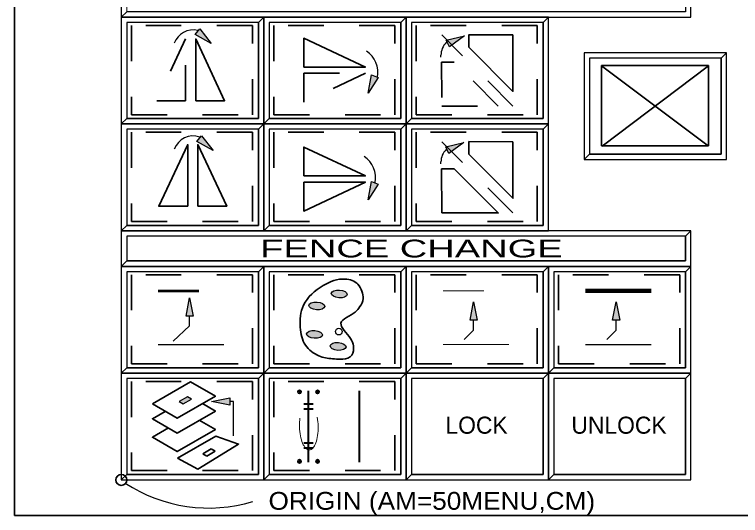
# Model space of a CAD drawing. Extents: x 95906.8 to 95923.6, y 90964.8 to 90972.8.
# Drawn here: x 95906.832 to 95908.871, y 90964.762 to 90966.169 of the extents above; entities that cross this region are included whole.
import ezdxf
from ezdxf.enums import TextEntityAlignment as Align

# ---------------------------------------------------------------- set-up
doc = ezdxf.new("R2010")
doc.units = 0
doc.header["$LTSCALE"] = 0.019
doc.header["$PDMODE"] = 32
doc.header["$PDSIZE"] = 0.0095
for name, pattern in [('DOTTED', [1.5, 0.3, -1.2]), ('LONG_DASHED', [7.5, 6, -1.5]), ('MEDIUM_DASHED', [4.5, 3, -1.5])]:
    doc.linetypes.add(name, pattern=pattern)
for name, color, linetype, lineweight in [('1', 7, 'Continuous', 25), ('11', 7, 'Continuous', 25), ('12', 7, 'Continuous', 25), ('16', 7, 'Continuous', 25), ('18', 7, 'Continuous', 25), ('2', 7, 'Continuous', 13), ('3', 7, 'Continuous', 25), ('6', 7, 'Continuous', 35), ('7', 7, 'Continuous', 35)]:
    doc.layers.add(name, color=color, linetype=linetype, lineweight=lineweight)

msp = doc.modelspace()

# ---------------------------------------------------------------- hatches: boundary and pattern name
at = {"layer": '6'}
for points in [[(95907.3851, 90966.0877), (95907.3396, 90966.1133), (95907.3529, 90966.1287)], [(95908.0958, 90966.1092), (95908.0537, 90966.0783), (95908.0451, 90966.0968)], [(95907.8257, 90965.9486), (95907.8349, 90966), (95907.8539, 90965.9925)], [(95907.3901, 90965.7871), (95907.3445, 90965.8126), (95907.3579, 90965.8282)], [(95908.0947, 90965.8094), (95908.0526, 90965.7785), (95908.044, 90965.797)], [(95907.8257, 90965.6486), (95907.8349, 90965.7), (95907.8539, 90965.6925)], [(95907.314, 90965.3216), (95907.3242, 90965.3728), (95907.3344, 90965.3216)], [(95908.1219, 90965.3617), (95908.1321, 90965.3105), (95908.1117, 90965.3105)], [(95908.5219, 90965.3617), (95908.5321, 90965.3105), (95908.5117, 90965.3105)], [(95907.3058, 90965.0753), (95907.3293, 90965.0889), (95907.3181, 90965.0953), (95907.2946, 90965.0817)], [(95907.3857, 90965.0817), (95907.4369, 90965.0919), (95907.4369, 90965.0715)]]:
    msp.add_hatch(color=256, dxfattribs=at).paths.add_polyline_path(points)
h = msp.add_hatch(color=256, dxfattribs=at)
edge = h.paths.add_edge_path()
edge.add_ellipse((95907.7443, 90965.3842), major_axis=(-0.0223, 0.0015), ratio=0.490241, start_angle=0, end_angle=360)
h = msp.add_hatch(color=256, dxfattribs=at)
edge = h.paths.add_edge_path()
edge.add_ellipse((95907.6812, 90965.3504), major_axis=(-0.0223, 0.0015), ratio=0.490241, start_angle=0, end_angle=360)
h = msp.add_hatch(color=256, dxfattribs=at)
edge = h.paths.add_edge_path()
edge.add_ellipse((95907.6751, 90965.2705), major_axis=(-0.0223, 0.0015), ratio=0.490241, start_angle=0, end_angle=360)
h = msp.add_hatch(color=256, dxfattribs=at)
edge = h.paths.add_edge_path()
edge.add_ellipse((95907.7412, 90965.2366), major_axis=(-0.0223, 0.0015), ratio=0.490241, start_angle=0, end_angle=360)

# ---------------------------------------------------------------- linework, layer by layer
at = {"layer": '1'}
for points in [[(95907.1323, 90966.1617), (95908.7323, 90966.1617), (95908.7323, 90966.2617), (95907.1323, 90966.2617)], [(95907.1323, 90965.8617), (95907.5323, 90965.8617), (95907.5323, 90966.1617), (95907.1323, 90966.1617)], [(95907.5323, 90965.8617), (95907.9323, 90965.8617), (95907.9323, 90966.1617), (95907.5323, 90966.1617)], [(95907.9323, 90965.8617), (95908.3323, 90965.8617), (95908.3323, 90966.1617), (95907.9323, 90966.1617)], [(95908.4323, 90965.7617), (95908.8323, 90965.7617), (95908.8323, 90966.0617), (95908.4323, 90966.0617)], [(95907.1323, 90965.5617), (95907.5323, 90965.5617), (95907.5323, 90965.8617), (95907.1323, 90965.8617)], [(95907.5323, 90965.5617), (95907.9323, 90965.5617), (95907.9323, 90965.8617), (95907.5323, 90965.8617)], [(95907.9323, 90965.5617), (95908.3323, 90965.5617), (95908.3323, 90965.8617), (95907.9323, 90965.8617)], [(95907.1323, 90965.4617), (95908.7323, 90965.4617), (95908.7323, 90965.5617), (95907.1323, 90965.5617)], [(95907.1323, 90965.1617), (95907.5323, 90965.1617), (95907.5323, 90965.4617), (95907.1323, 90965.4617)], [(95907.5323, 90965.1617), (95907.9323, 90965.1617), (95907.9323, 90965.4617), (95907.5323, 90965.4617)], [(95907.9323, 90965.1617), (95908.3323, 90965.1617), (95908.3323, 90965.4617), (95907.9323, 90965.4617)], [(95908.3323, 90965.1617), (95908.7323, 90965.1617), (95908.7323, 90965.4617), (95908.3323, 90965.4617)], [(95907.1323, 90964.8617), (95907.5323, 90964.8617), (95907.5323, 90965.1617), (95907.1323, 90965.1617)], [(95907.5323, 90964.8617), (95907.9323, 90964.8617), (95907.9323, 90965.1617), (95907.5323, 90965.1617)], [(95907.9323, 90964.8617), (95908.3323, 90964.8617), (95908.3323, 90965.1617), (95907.9323, 90965.1617)], [(95908.3323, 90964.8617), (95908.7323, 90964.8617), (95908.7323, 90965.1617), (95908.3323, 90965.1617)]]:
    msp.add_lwpolyline(points, close=True, dxfattribs=at)
at = {"layer": '11'}
for points in [[(95907.5473, 90965.8767), (95907.9173, 90965.8767), (95907.9173, 90966.1467), (95907.5473, 90966.1467)], [(95907.9473, 90965.8767), (95908.3173, 90965.8767), (95908.3173, 90966.1467), (95907.9473, 90966.1467)], [(95907.1473, 90965.5767), (95907.5173, 90965.5767), (95907.5173, 90965.8467), (95907.1473, 90965.8467)], [(95907.5473, 90965.5767), (95907.9173, 90965.5767), (95907.9173, 90965.8467), (95907.5473, 90965.8467)], [(95907.9473, 90965.5767), (95908.3173, 90965.5767), (95908.3173, 90965.8467), (95907.9473, 90965.8467)], [(95907.1473, 90965.1767), (95907.5173, 90965.1767), (95907.5173, 90965.4467), (95907.1473, 90965.4467)], [(95907.5473, 90965.1767), (95907.9173, 90965.1767), (95907.9173, 90965.4467), (95907.5473, 90965.4467)], [(95907.9473, 90965.1767), (95908.3173, 90965.1767), (95908.3173, 90965.4467), (95907.9473, 90965.4467)], [(95907.1473, 90964.8767), (95907.5173, 90964.8767), (95907.5173, 90965.1467), (95907.1473, 90965.1467)], [(95907.5473, 90964.8767), (95907.9173, 90964.8767), (95907.9173, 90965.1467), (95907.5473, 90965.1467)], [(95907.9473, 90964.8767), (95908.3173, 90964.8767), (95908.3173, 90965.1467), (95907.9473, 90965.1467)], [(95908.3473, 90964.8767), (95908.7173, 90964.8767), (95908.7173, 90965.1467), (95908.3473, 90965.1467)]]:
    msp.add_lwpolyline(points, close=True, dxfattribs=at)
at = {"layer": '12'}
for points in [[(95907.1473, 90965.8767), (95907.5173, 90965.8767), (95907.5173, 90966.1467), (95907.1473, 90966.1467)], [(95908.3473, 90965.1767), (95908.7173, 90965.1767), (95908.7173, 90965.4467), (95908.3473, 90965.4467)]]:
    msp.add_lwpolyline(points, close=True, dxfattribs=at)
at = {"layer": '16'}
msp.add_lwpolyline([(95908.4473, 90965.7767), (95908.8173, 90965.7767), (95908.8173, 90966.0467), (95908.4473, 90966.0467)], close=True, dxfattribs=at)
msp.add_lwpolyline([(95908.4473, 90965.7767), (95908.8173, 90965.7767), (95908.8173, 90966.0467), (95908.4473, 90966.0467)], close=True, dxfattribs=at)
at = {"layer": '18'}
msp.add_lwpolyline([(95907.1473, 90965.4767), (95908.7173, 90965.4767), (95908.7173, 90965.5467), (95907.1473, 90965.5467)], close=True, dxfattribs=at)
at = {"layer": '2'}
for points in [[(95907.1323, 90966.2617), (95907.1323, 90966.1617), (95907.1473, 90966.1767), (95907.1473, 90966.2467), (95908.7173, 90966.2467), (95908.7323, 90966.2617)], [(95907.1323, 90966.1617), (95907.1323, 90965.8617), (95907.1473, 90965.8767), (95907.1473, 90966.1467), (95907.5173, 90966.1467), (95907.5323, 90966.1617)], [(95907.5323, 90966.1617), (95907.5323, 90965.8617), (95907.5473, 90965.8767), (95907.5473, 90966.1467), (95907.9173, 90966.1467), (95907.9323, 90966.1617)], [(95907.9323, 90966.1617), (95907.9323, 90965.8617), (95907.9473, 90965.8767), (95907.9473, 90966.1467), (95908.3173, 90966.1467), (95908.3323, 90966.1617)], [(95908.4323, 90966.0617), (95908.4323, 90965.7617), (95908.4473, 90965.7767), (95908.4473, 90966.0467), (95908.8173, 90966.0467), (95908.8323, 90966.0617)], [(95907.1323, 90965.8617), (95907.1323, 90965.5617), (95907.1473, 90965.5767), (95907.1473, 90965.8467), (95907.5173, 90965.8467), (95907.5323, 90965.8617)], [(95907.5323, 90965.8617), (95907.5323, 90965.5617), (95907.5473, 90965.5767), (95907.5473, 90965.8467), (95907.9173, 90965.8467), (95907.9323, 90965.8617)], [(95907.9323, 90965.8617), (95907.9323, 90965.5617), (95907.9473, 90965.5767), (95907.9473, 90965.8467), (95908.3173, 90965.8467), (95908.3323, 90965.8617)], [(95907.1323, 90965.5617), (95907.1323, 90965.4617), (95907.1473, 90965.4767), (95907.1473, 90965.5467), (95908.7173, 90965.5467), (95908.7323, 90965.5617)], [(95907.1323, 90965.4617), (95907.1323, 90965.1617), (95907.1473, 90965.1767), (95907.1473, 90965.4467), (95907.5173, 90965.4467), (95907.5323, 90965.4617)], [(95907.5323, 90965.4617), (95907.5323, 90965.1617), (95907.5473, 90965.1767), (95907.5473, 90965.4467), (95907.9173, 90965.4467), (95907.9323, 90965.4617)], [(95907.9323, 90965.4617), (95907.9323, 90965.1617), (95907.9473, 90965.1767), (95907.9473, 90965.4467), (95908.3173, 90965.4467), (95908.3323, 90965.4617)], [(95908.3323, 90965.4617), (95908.3323, 90965.1617), (95908.3473, 90965.1767), (95908.3473, 90965.4467), (95908.7173, 90965.4467), (95908.7323, 90965.4617)], [(95907.1323, 90965.1617), (95907.1323, 90964.8617), (95907.1473, 90964.8767), (95907.1473, 90965.1467), (95907.5173, 90965.1467), (95907.5323, 90965.1617)], [(95907.5323, 90965.1617), (95907.5323, 90964.8617), (95907.5473, 90964.8767), (95907.5473, 90965.1467), (95907.9173, 90965.1467), (95907.9323, 90965.1617)], [(95907.9323, 90965.1617), (95907.9323, 90964.8617), (95907.9473, 90964.8767), (95907.9473, 90965.1467), (95908.3173, 90965.1467), (95908.3323, 90965.1617)], [(95908.3323, 90965.1617), (95908.3323, 90964.8617), (95908.3473, 90964.8767), (95908.3473, 90965.1467), (95908.7173, 90965.1467), (95908.7323, 90965.1617)]]:
    msp.add_lwpolyline(points, close=True, dxfattribs=at)
at = {"layer": '3'}
for points in [[(95907.1323, 90966.1617), (95908.7323, 90966.1617), (95908.7323, 90966.2617), (95908.7173, 90966.2467), (95908.7173, 90966.1767), (95907.1473, 90966.1767)], [(95907.1323, 90965.8617), (95907.5323, 90965.8617), (95907.5323, 90966.1617), (95907.5173, 90966.1467), (95907.5173, 90965.8767), (95907.1473, 90965.8767)], [(95907.5323, 90965.8617), (95907.9323, 90965.8617), (95907.9323, 90966.1617), (95907.9173, 90966.1467), (95907.9173, 90965.8767), (95907.5473, 90965.8767)], [(95907.9323, 90965.8617), (95908.3323, 90965.8617), (95908.3323, 90966.1617), (95908.3173, 90966.1467), (95908.3173, 90965.8767), (95907.9473, 90965.8767)], [(95908.4323, 90965.7617), (95908.8323, 90965.7617), (95908.8323, 90966.0617), (95908.8173, 90966.0467), (95908.8173, 90965.7767), (95908.4473, 90965.7767)], [(95907.1323, 90965.5617), (95907.5323, 90965.5617), (95907.5323, 90965.8617), (95907.5173, 90965.8467), (95907.5173, 90965.5767), (95907.1473, 90965.5767)], [(95907.5323, 90965.5617), (95907.9323, 90965.5617), (95907.9323, 90965.8617), (95907.9173, 90965.8467), (95907.9173, 90965.5767), (95907.5473, 90965.5767)], [(95907.9323, 90965.5617), (95908.3323, 90965.5617), (95908.3323, 90965.8617), (95908.3173, 90965.8467), (95908.3173, 90965.5767), (95907.9473, 90965.5767)], [(95907.1323, 90965.4617), (95908.7323, 90965.4617), (95908.7323, 90965.5617), (95908.7173, 90965.5467), (95908.7173, 90965.4767), (95907.1473, 90965.4767)], [(95907.1323, 90965.1617), (95907.5323, 90965.1617), (95907.5323, 90965.4617), (95907.5173, 90965.4467), (95907.5173, 90965.1767), (95907.1473, 90965.1767)], [(95907.5323, 90965.1617), (95907.9323, 90965.1617), (95907.9323, 90965.4617), (95907.9173, 90965.4467), (95907.9173, 90965.1767), (95907.5473, 90965.1767)], [(95907.9323, 90965.1617), (95908.3323, 90965.1617), (95908.3323, 90965.4617), (95908.3173, 90965.4467), (95908.3173, 90965.1767), (95907.9473, 90965.1767)], [(95908.3323, 90965.1617), (95908.7323, 90965.1617), (95908.7323, 90965.4617), (95908.7173, 90965.4467), (95908.7173, 90965.1767), (95908.3473, 90965.1767)], [(95907.1323, 90964.8617), (95907.5323, 90964.8617), (95907.5323, 90965.1617), (95907.5173, 90965.1467), (95907.5173, 90964.8767), (95907.1473, 90964.8767)], [(95907.5323, 90964.8617), (95907.9323, 90964.8617), (95907.9323, 90965.1617), (95907.9173, 90965.1467), (95907.9173, 90964.8767), (95907.5473, 90964.8767)], [(95907.9323, 90964.8617), (95908.3323, 90964.8617), (95908.3323, 90965.1617), (95908.3173, 90965.1467), (95908.3173, 90964.8767), (95907.9473, 90964.8767)], [(95908.3323, 90964.8617), (95908.7323, 90964.8617), (95908.7323, 90965.1617), (95908.7173, 90965.1467), (95908.7173, 90964.8767), (95908.3473, 90964.8767)]]:
    msp.add_lwpolyline(points, close=True, dxfattribs=at)
at = {"layer": '6', "linetype": 'MEDIUM_DASHED'}
for p, q in [((95908.2323, 90965.9117), (95908.0323, 90966.1117)), ((95908.2323, 90965.6117), (95908.0323, 90965.8117))]:
    msp.add_line(p, q, dxfattribs=at)
at = {"layer": '6', "lineweight": 25}
for p, q in [((95908.0447, 90966.0902), (95908.0493, 90966.0948)), ((95908.0301, 90966.0495), (95908.0301, 90966.0549)), ((95908.0301, 90965.7495), (95908.0301, 90965.7549)), ((95907.2361, 90965.2424), (95907.4205, 90965.2424)), ((95908.4361, 90965.2424), (95908.6205, 90965.2424))]:
    msp.add_line(p, q, dxfattribs=at)
at = {"layer": '6'}
for p, q in [((95908.4809, 90966.0252), (95908.7809, 90965.8002)), ((95908.4824, 90965.799), (95908.7815, 90966.0252))]:
    msp.add_line(p, q, dxfattribs=at)
at = {"layer": '6', "linetype": 'LONG_DASHED', "lineweight": 53}
msp.add_line((95907.2361, 90965.393), (95907.4205, 90965.393), dxfattribs=at)
at = {"layer": '6', "linetype": 'LONG_DASHED', "lineweight": 13}
msp.add_line((95908.0361, 90965.393), (95908.2205, 90965.393), dxfattribs=at)
at = {"layer": '6', "lineweight": 158}
msp.add_line((95908.4361, 90965.393), (95908.6205, 90965.393), dxfattribs=at)
at = {"layer": '6', "lineweight": 13}
msp.add_line((95908.0361, 90965.2424), (95908.2205, 90965.2424), dxfattribs=at)
at = {"layer": '6', "lineweight": 40}
for p, q in [((95907.6573, 90965.1117), (95907.6573, 90964.9117)), ((95907.8003, 90965.1117), (95907.8003, 90964.9117)), ((95907.6451, 90965.0752), (95907.6713, 90965.0752)), ((95907.6451, 90965.0614), (95907.6713, 90965.0614)), ((95907.6451, 90964.9661), (95907.6713, 90964.9661)), ((95907.6451, 90964.9522), (95907.6713, 90964.9522))]:
    msp.add_line(p, q, dxfattribs=at)
at = {"layer": '6', "linetype": 'DOTTED'}
for points in [[(95907.5007, 90966.1382), (95907.1606, 90966.1382), (95907.1606, 90965.8878), (95907.5007, 90965.8878)], [(95907.9007, 90966.1382), (95907.5606, 90966.1382), (95907.5606, 90965.8878), (95907.9007, 90965.8878)], [(95908.3007, 90966.1382), (95907.9606, 90966.1382), (95907.9606, 90965.8878), (95908.3007, 90965.8878)], [(95907.5007, 90965.8382), (95907.1606, 90965.8382), (95907.1606, 90965.5878), (95907.5007, 90965.5878)], [(95907.9007, 90965.8382), (95907.5606, 90965.8382), (95907.5606, 90965.5878), (95907.9007, 90965.5878)], [(95908.3007, 90965.8382), (95907.9606, 90965.8382), (95907.9606, 90965.5878), (95908.3007, 90965.5878)], [(95907.5007, 90965.4382), (95907.1606, 90965.4382), (95907.1606, 90965.1878), (95907.5007, 90965.1878)], [(95907.9007, 90965.4382), (95907.5606, 90965.4382), (95907.5606, 90965.1878), (95907.9007, 90965.1878)], [(95908.3007, 90965.4382), (95907.9606, 90965.4382), (95907.9606, 90965.1878), (95908.3007, 90965.1878)], [(95908.7007, 90965.4382), (95908.3606, 90965.4382), (95908.3606, 90965.1878), (95908.7007, 90965.1878)], [(95907.5007, 90965.1382), (95907.1606, 90965.1382), (95907.1606, 90964.8878), (95907.5007, 90964.8878)], [(95907.9007, 90965.1382), (95907.5606, 90965.1382), (95907.5606, 90964.8878), (95907.9007, 90964.8878)]]:
    msp.add_lwpolyline(points, close=True, dxfattribs=at)
at = {"layer": '6', "lineweight": 25}
for points in [[(95907.3851, 90966.0877), (95907.3396, 90966.1133), (95907.3529, 90966.1287)], [(95908.0958, 90966.1092), (95908.0537, 90966.0783), (95908.0451, 90966.0968)], [(95907.8257, 90965.9486), (95907.8349, 90966), (95907.8539, 90965.9925)], [(95907.3901, 90965.7871), (95907.3445, 90965.8126), (95907.3579, 90965.8282)], [(95908.0947, 90965.8094), (95908.0526, 90965.7785), (95908.044, 90965.797)], [(95907.8257, 90965.6486), (95907.8349, 90965.7), (95907.8539, 90965.6925)], [(95907.314, 90965.3216), (95907.3242, 90965.3728), (95907.3344, 90965.3216)], [(95908.1219, 90965.3617), (95908.1321, 90965.3105), (95908.1117, 90965.3105)], [(95908.5219, 90965.3617), (95908.5321, 90965.3105), (95908.5117, 90965.3105)], [(95907.3058, 90965.0753), (95907.3293, 90965.0889), (95907.3181, 90965.0953), (95907.2946, 90965.0817)], [(95907.3857, 90965.0817), (95907.4369, 90965.0919), (95907.4369, 90965.0715)]]:
    msp.add_lwpolyline(points, close=True, dxfattribs=at)
at = {"layer": '6'}
for points in [[(95907.6447, 90966.0216), (95907.818, 90966.0216), (95907.6447, 90966.1027)], [(95908.2324, 90966.1118), (95908.2324, 90965.9532), (95908.1085, 90966.0771), (95908.1085, 90966.1124)], [(95907.3412, 90965.9271), (95907.3412, 90966.1005), (95907.4224, 90965.9271)], [(95908.4812, 90965.8006), (95908.7812, 90965.8006), (95908.7812, 90966.0256), (95908.4812, 90966.0256)], [(95907.3187, 90965.6303), (95907.3187, 90965.8037), (95907.2376, 90965.6303)], [(95907.347, 90965.6303), (95907.347, 90965.8037), (95907.4282, 90965.6303)], [(95907.6447, 90965.7158), (95907.818, 90965.7158), (95907.6447, 90965.7969)], [(95908.2324, 90965.8118), (95908.2324, 90965.6532), (95908.1085, 90965.7771), (95908.1085, 90965.8124)], [(95908.0323, 90965.6117), (95908.1909, 90965.6117), (95908.067, 90965.7356), (95908.0317, 90965.7356)], [(95907.6447, 90965.6982), (95907.818, 90965.6982), (95907.6447, 90965.617)], [(95907.2197, 90965.0752), (95907.3267, 90965.137), (95907.3965, 90965.0967), (95907.2895, 90965.0349)], [(95907.2904, 90964.923), (95907.3974, 90964.9848), (95907.4617, 90964.9625), (95907.3468, 90964.8921)]]:
    msp.add_lwpolyline(points, close=True, dxfattribs=at)
at = {"layer": '6', "linetype": 'MEDIUM_DASHED'}
for points in [[(95907.3129, 90965.9271), (95907.3129, 90966.1005), (95907.2318, 90965.9271)], [(95908.0323, 90965.9117), (95908.1909, 90965.9117), (95908.067, 90966.0356), (95908.0317, 90966.0356)], [(95907.6447, 90966.004), (95907.818, 90966.004), (95907.6447, 90965.9228)], [(95907.3724, 90964.9288), (95907.3959, 90964.9424), (95907.3847, 90964.9488), (95907.3612, 90964.9352)]]:
    msp.add_lwpolyline(points, close=True, dxfattribs=at)
at = {"layer": '6', "lineweight": 25}
for points in [[(95907.2779, 90965.2514), (95907.3242, 90965.2948), (95907.3242, 90965.3216)], [(95908.0956, 90965.2564), (95908.1219, 90965.2827), (95908.1219, 90965.3105)], [(95908.4956, 90965.2564), (95908.5219, 90965.2827), (95908.5219, 90965.3105)], [(95907.4476, 90964.9856), (95907.4476, 90965.0823), (95907.4369, 90965.0823)]]:
    msp.add_lwpolyline(points, dxfattribs=at)
at = {"layer": '6'}
for points in [[(95907.3602, 90965.0763), (95907.3965, 90965.0552), (95907.2895, 90964.9934), (95907.2197, 90965.0337), (95907.2554, 90965.0543)], [(95907.3511, 90965.0292), (95907.3965, 90965.0029), (95907.2895, 90964.9411), (95907.2197, 90964.9814), (95907.265, 90965.0076)]]:
    msp.add_lwpolyline(points, dxfattribs=at)
at = {"layer": '6', "lineweight": 25}
msp.add_circle((95907.7435, 90965.2782), 0.00934, dxfattribs=at)
for centre, radius, start, end in [((95907.334, 90966.0697), 0.0561, 76.2295, 160.6007), ((95908.0801, 90966.0549), 0.05, 135, 180), ((95907.7804, 90966.0054), 0.0727, 350.0158, 56.4113), ((95907.334, 90965.772), 0.0561, 70.6376, 160.6007), ((95908.0801, 90965.7549), 0.05, 135, 180), ((95907.7739, 90965.7097), 0.0727, 350.0158, 56.4113)]:
    msp.add_arc(centre, radius, start, end, dxfattribs=at)
for centre in [(95907.7443, 90965.3842), (95907.6812, 90965.3504), (95907.6751, 90965.2705), (95907.7412, 90965.2366)]:
    msp.add_ellipse(centre, major_axis=(-0.0223, 0.0015), ratio=0.490241, dxfattribs=at)
at = {"layer": '6', "linetype": 'MEDIUM_DASHED', "lineweight": 13}
msp.add_ellipse((95907.6589, 90965.0115), major_axis=(0.0015, -0.0654), ratio=0.400869, dxfattribs=at)
at = {"layer": '6'}
msp.add_spline([(95907.749, 90965.2007), (95907.7252, 90965.2021), (95907.6874, 90965.2101), (95907.6496, 90965.2402), (95907.6349, 90965.2905), (95907.6439, 90965.3524), (95907.6993, 90965.4078), (95907.7611, 90965.426), (95907.7969, 90965.4116), (95907.8079, 90965.3915), (95907.8119, 90965.3711), (95907.8026, 90965.3484), (95907.7892, 90965.333), (95907.7493, 90965.3022), (95907.7761, 90965.259), (95907.7842, 90965.2379), (95907.7795, 90965.2118), (95907.7547, 90965.2007), (95907.749, 90965.2007)], degree=3, dxfattribs=at)
for p in [(95907.6328, 90965.109), (95907.6836, 90965.109), (95907.6328, 90964.9138), (95907.6836, 90964.9138)]:
    msp.add_point(p, dxfattribs=at)
at = {"layer": '7'}
msp.add_lwpolyline([(95906.8323, 90972.7617), (95918.8323, 90972.7617), (95918.8323, 90964.7617), (95906.8323, 90964.7617)], close=True, dxfattribs=at)
msp.add_circle((95907.1323, 90964.8617), 0.0154, dxfattribs=at)
at = {"layer": '7', "lineweight": 25}
msp.add_arc((95907.3775, 90965.209), 0.4264, 236.6831, 286.8865, dxfattribs=at)

# ---------------------------------------------------------------- texts
at = {"layer": '6'}
for s, p in [('LOCK', (95908.1301, 90964.9914)), ('UNLOCK', (95908.5302, 90964.9914))]:
    msp.add_text(s, height=0.048, dxfattribs=at).set_placement(p, align=Align.CENTER)
at = {"layer": '7'}
for s, height, width, p in [('      FENCE CHANGE     ', 0.04999, 1.6, (95907.9322, 90965.4867)), ('ORIGIN (AM=50MENU,CM)', 0.05, 1.1, (95908.0044, 90964.7778))]:
    msp.add_text(s, height=height, dxfattribs=dict(at, width=width)).set_placement(p, align=Align.CENTER)

doc.saveas('drawing.dxf')
